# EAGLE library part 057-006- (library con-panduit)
CONNECTOR 6-pin series 057 contact pc board low profile headers
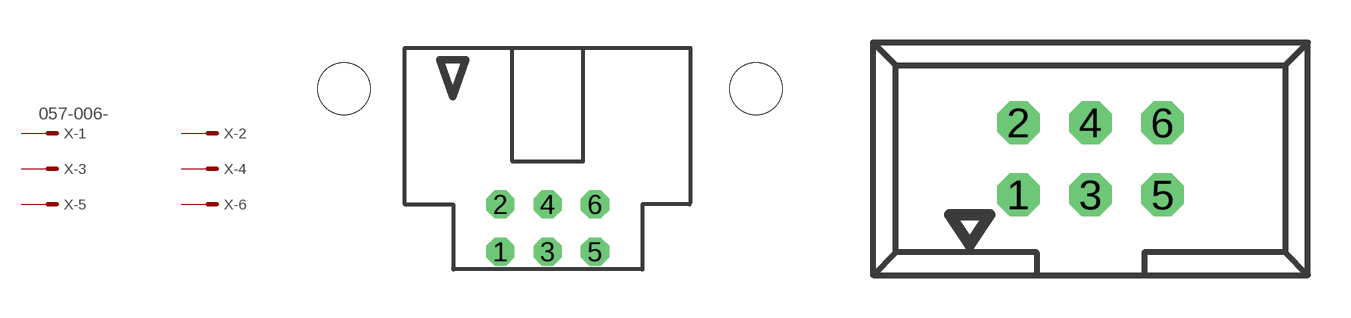
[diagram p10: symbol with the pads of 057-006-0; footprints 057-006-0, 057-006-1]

Designator prefix X; gates -1=MV -2=M -3=M -4=M -5=M -6=M

## 057-006-0 (OC_FARNELL: unknown; OC_NEWARK: unknown)  [057-006-0]
1  -1:S  pas
2  -2:S  pas
3  -3:S  pas
4  -4:S  pas
5  -5:S  pas
6  -6:S  pas

## 057-006-1 (OC_FARNELL: unknown; OC_NEWARK: unknown)  [057-006-1]
Pads as for 057-006-0

## Footprint 057-006-0 (pad centres in mm)
CONNECTOR series 057 contact pc board low profile headers angled
drill 1 octagon: 1 -2.54,-5.08; 2 -2.54,-2.54; 3 0,-5.08; 4 0,-2.54; 5 2.54,-5.08; 6 2.54,-2.54
hole 2.8 at -10.94,3.66
hole 2.8 at 11.19,3.66

## Footprint 057-006-1 (pad centres in mm)
CONNECTOR series 057 contact pc board low profile headers straight
drill 1 octagon: 1 -2.54,-1.27; 2 -2.54,1.27; 3 0,-1.27; 4 0,1.27; 5 2.54,-1.27; 6 2.54,1.27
